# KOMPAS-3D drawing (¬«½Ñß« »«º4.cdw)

Referenced files in C:\редуктор\Полноценные\цилиндрические\задание 1103\: колесо-1103.cdw
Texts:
  Колесо зубчатое
  125 1 126 1 127 1 128 0 50 1|SPDS|125 1 126 1 127 1 128 0 50 1
  129 1 130 1 131 1 132 0 50 1|SPDS|129 1 130 1 131 1 132 0 50 1
  Ra3.2
  Js10
  Модуль нормальный
  Число зубьев
  Угол наклона зуба
  Symbol type A
  Направление зуба
  левое
  Исходный контур
  ГОСТ 13755-81
  Коэффициент смещения
  исходного контура
  Степень точности
  по ГОСТ 1643-81
  Делительный диаметр
  Обозначение чертежа
  сопряженной шестерни
  ОКМА.1001.
  1. Термообработка, улучшение НВ 210.
  2. Неуказанные предельные отклонения размеров:
  отверстий по Н14, валов по h14.
  3. Острые кромки притупить R   0,3.
  Ra6.3
  Сталь 45 ГОСТ 1050-88
  ДГТУ
  Кафедра "ОКМ"
Dimensions and other numbers on the sheet: 0; 15; 4 отв.; 0,005; 0,12; 0,3; 14; 2; 76; 10 51'; 8-С; 154.764; 0100.005; 2 фаски; 7; 44,8; 1; 67; 72; 15,4; 134; 104; 158,76; 48,8; 40; 1:1; 2.52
